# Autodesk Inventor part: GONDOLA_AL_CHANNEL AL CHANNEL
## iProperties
Shininess: 64.0
Length Units: 11272
Angle Units: 11279
Time Units: 11290
Mass Units: 11286
Length Display Precision: 3
Angle Display Precision: 2
Compacted: True
Part Number: GONDOLA_AL_CHANNEL AL CHANNEL
Document SubType Name: Modeling
Created: 2004-08
Designer: John Blackburn
Material: ALUMINUM
Manufacturer: Standard
Standards Organization: Custom
Density: 0.0
Volumn: 0.0
Area: 0.0
PropertySet Name: Model Information
Control State: 0
Master: False
Checked Out: False
Author: John Blackburn
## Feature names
1. Base1
